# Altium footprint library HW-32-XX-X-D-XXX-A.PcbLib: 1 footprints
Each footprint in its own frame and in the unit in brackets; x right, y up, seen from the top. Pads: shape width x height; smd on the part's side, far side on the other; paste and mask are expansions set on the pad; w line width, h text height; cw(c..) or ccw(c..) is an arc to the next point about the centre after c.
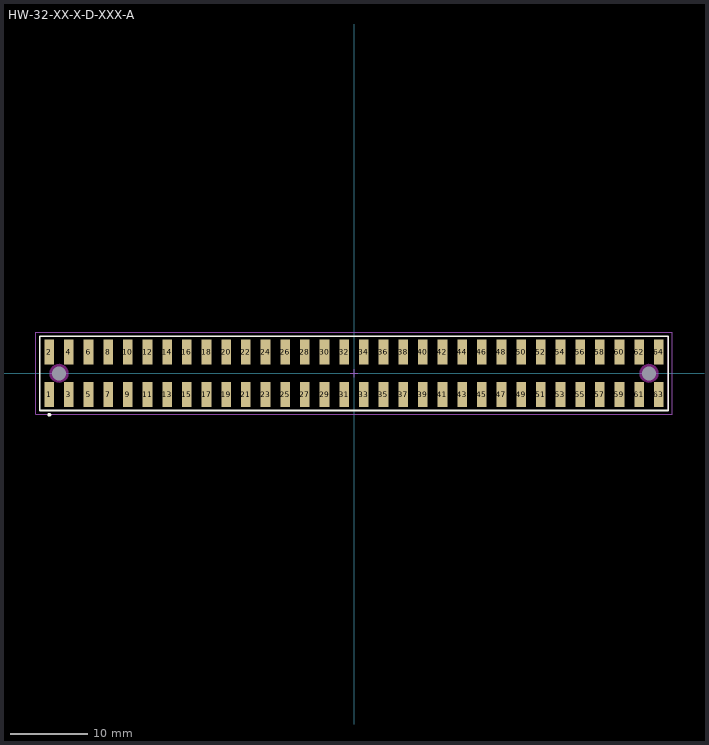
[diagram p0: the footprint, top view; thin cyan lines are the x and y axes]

## HW-32-XX-X-D-XXX-A [mm] "2.54mm pitch, 64 pin, board stacker; double row, w/alignment pins, SMT"
height 9.65
pads (66):
  rect 1.25x3.2 smd mask+0: 1(-39.37,-2.75) 2(-39.37,2.75) 3(-36.83,-2.75) 4(-36.83,2.75) 5(-34.29,-2.75) 6(-34.29,2.75) 7(-31.75,-2.75) 8(-31.75,2.75) 9(-29.21,-2.75) 10(-29.21,2.75) 11(-26.67,-2.75) 12(-26.67,2.75) 13(-24.13,-2.75) 14(-24.13,2.75) 15(-21.59,-2.75) 16(-21.59,2.75) 17(-19.05,-2.75) 18(-19.05,2.75) 19(-16.51,-2.75) 20(-16.51,2.75) 21(-13.97,-2.75) 22(-13.97,2.75) 23(-11.43,-2.75) 24(-11.43,2.75) 25(-8.89,-2.75) 26(-8.89,2.75) 27(-6.35,-2.75) 28(-6.35,2.75) 29(-3.81,-2.75) 30(-3.81,2.75) 31(-1.27,-2.75) 32(-1.27,2.75) 33(1.27,-2.75) 34(1.27,2.75) 35(3.81,-2.75) 36(3.81,2.75) 37(6.35,-2.75) 38(6.35,2.75) 39(8.89,-2.75) 40(8.89,2.75) 41(11.43,-2.75) 42(11.43,2.75) 43(13.97,-2.75) 44(13.97,2.75) 45(16.51,-2.75) 46(16.51,2.75) 47(19.05,-2.75) 48(19.05,2.75) 49(21.59,-2.75) 50(21.59,2.75) 51(24.13,-2.75) 52(24.13,2.75) 53(26.67,-2.75) 54(26.67,2.75) 55(29.21,-2.75) 56(29.21,2.75) 57(31.75,-2.75) 58(31.75,2.75) 59(34.29,-2.75) 60(34.29,2.75) 61(36.83,-2.75) 62(36.83,2.75) 63(39.37,-2.75) 64(39.37,2.75)
  round 1 hole 1.8 unplated mask+0: 65(38.1,0) 66(-38.1,0)
Top Overlay:
  circle w0.25: c-39.35,-5.35 r0.125
  lines w0.2: -40.6,-4.8 40.6,-4.8 40.6,4.8 -40.6,4.8 -40.6,-4.8
Keep-Out Layer:
  pour cut-out: -36.89,0 -36.931,0.313 -37.052,0.605 -37.244,0.856 -37.495,1.048 -37.787,1.169 -38.1,1.21 -38.413,1.169 -38.705,1.048 -38.956,0.856 -39.148,0.605 -39.269,0.313 -39.31,0 -39.269,-0.313 -39.148,-0.605 -38.956,-0.856 -38.705,-1.048 -38.413,-1.169 -38.1,-1.21 -37.787,-1.169 -37.495,-1.048 -37.244,-0.856 -37.052,-0.605 -36.931,-0.313
  pour cut-out: 39.31,0 39.269,0.313 39.148,0.605 38.956,0.856 38.705,1.048 38.413,1.169 38.1,1.21 37.787,1.169 37.495,1.048 37.244,0.856 37.052,0.605 36.931,0.313 36.89,0 36.931,-0.313 37.052,-0.605 37.244,-0.856 37.495,-1.048 37.787,-1.169 38.1,-1.21 38.413,-1.169 38.705,-1.048 38.956,-0.856 39.148,-0.605 39.269,-0.313
Mechanical 12:
  lines w0.001: -40.6,-4.8 40.6,-4.8 40.6,4.8 -40.6,4.8 -40.6,-4.8
Mechanical 13:
  lines w0.1: -40.6,-4.8 40.6,-4.8 40.6,4.8 -40.6,4.8 -40.6,-4.8
  text ".Designator" at 0.254,0.381 h1.52
Mechanical 15:
  lines w0.05: -0.5,0 0.5,0 ; 0,-0.5 0,0.5 ; -41.1,-5.3 -41.1,5.3 41.1,5.3 41.1,-5.3 -41.1,-5.3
